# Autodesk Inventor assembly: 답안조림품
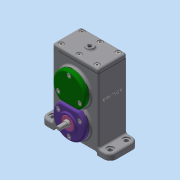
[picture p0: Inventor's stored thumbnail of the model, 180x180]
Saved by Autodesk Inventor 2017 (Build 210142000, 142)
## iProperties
Part Number: 답안조림품
Material: 일반
Document SubType Name: Assembly
Designer: mrc
Mass: 1460.95 g
Surface Area: 1575.48 cm^2
Volume: 385.032 cm^3
Density: 3.79437 g/cm^3
Author: mrc
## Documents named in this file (24)
- C:\Users\mrc\Desktop\600506V1034\답안조림품.iam
- C:\Users\mrc\Desktop\600506V1034\본체.ipt
- C:\Users\mrc\Desktop\600506V1034\개스킷 A.ipt
- C:\Users\mrc\Desktop\600506V1034\개스킷 B.ipt
- C:\Users\mrc\Desktop\600506V1034\개스킷 C.ipt
- C:\Users\mrc\Desktop\600506V1034\베어링 6001.ipt
- 베어링 6001.ipt
- C:\Users\mrc\Desktop\600506V1034\베어링 6002.ipt
- 베어링 6002.ipt
- C:\Users\mrc\Desktop\600506V1034\볼트 M4.ipt
- C:\Users\mrc\Desktop\600506V1034\스퍼기어 A.ipt
- C:\Users\mrc\Desktop\600506V1034\스퍼기어 B.ipt
- C:\Users\mrc\Desktop\600506V1034\오일 실 10 20 7.ipt
- C:\Users\mrc\Desktop\600506V1034\오일 실 12 22 7.ipt
- C:\Users\mrc\Desktop\600506V1034\축 A.ipt
- C:\Users\mrc\Desktop\600506V1034\축 B.ipt
- C:\Users\mrc\Desktop\600506V1034\칼라.ipt
- C:\Users\mrc\Desktop\600506V1034\커버 A.ipt
- C:\Users\mrc\Desktop\600506V1034\커버 B.ipt
- C:\Users\mrc\Desktop\600506V1034\커버 C.ipt
- C:\Users\mrc\Desktop\600506V1034\커버 D.ipt
- C:\Users\mrc\Desktop\600506V1034\커버 E.ipt
- C:\Users\mrc\Desktop\600506V1034\키 4 x 4 x 12.ipt
- C:\Users\mrc\Desktop\600506V1034\키 5 x 5 x 12.ipt
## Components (5 placed, 3 different names)
1. 개스킷 A:1
2. 개스킷 B:1
3. 개스킷 C:1
4. 개스킷 B:2
5. 개스킷 B:3
